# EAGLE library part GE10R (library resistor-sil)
SIL RESISTOR
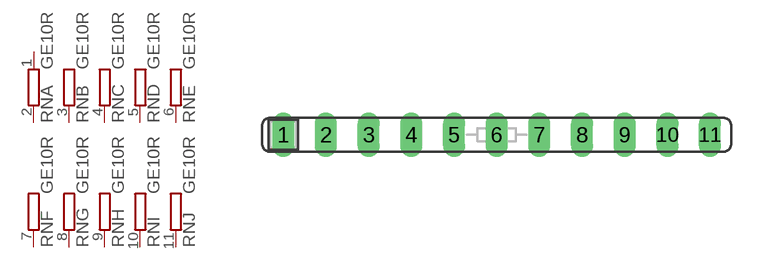
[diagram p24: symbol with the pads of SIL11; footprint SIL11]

Designator prefix RN; gates A=R-NV B=R-NV1 C=R-NV1 D=R-NV1 E=R-NV1 F=R-NV1 G=R-NV1 H=R-NV1 I=R-NV1 J=R-NV1

## GE10R (OC_FARNELL: unknown; OC_NEWARK: unknown)  [SIL11]
1  A:1  pas
2  A:2  pas
3  B:2  pas
4  C:2  pas
5  D:2  pas
6  E:2  pas
7  F:2  pas
8  G:2  pas
9  H:2  pas
10  I:2  pas
11  J:2  pas

## Footprint SIL11 (pad centres in mm)
Single In Line
drill 0.813 long: 1 -12.7,0; 2 -10.16,0; 3 -7.62,0; 4 -5.08,0; 5 -2.54,0; 6 0,0; 7 2.54,0; 8 5.08,0; 9 7.62,0; 10 10.16,0; 11 12.7,0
